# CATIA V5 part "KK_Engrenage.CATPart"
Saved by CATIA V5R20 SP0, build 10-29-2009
Part number: Engrenage
Bounding box of the stored display mesh (mm): x 5 to 10, y 76.002 to 123.998, z -23.997 to 23.997
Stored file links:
  G:\Khaled_CFAO_2011\ST2M\ST2M_GR2\aandujar\Khaled\CAD_thinkMOTION\KK_Engrenage.CATPart
  G:\Khaled_CFAO_2011\ST2M\ST2M_GR2\aandujar\Khaled\CAD_thinkMOTION\KK_Aandujar.CATProduct
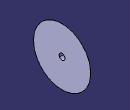
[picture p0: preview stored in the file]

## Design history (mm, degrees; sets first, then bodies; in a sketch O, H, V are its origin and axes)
WSupportSet1: ActiveGrid {3dwsupport RefPoint {point stored without definition}, 3DWOS ({wsupport Support xy-plane, RefPoint {3dwsupport}, GridIn {cartgrid Value 100, Stepbid1 0, Value 100, Stepbid2 0, Direction (1, 0, 0)}, GeometricData ({line type PtDir, Direction (1, 0, 0), Support xy-plane}; {line type PtDir, Direction (0, 1, 0), Support yz-plane})}; {wsupport Support yz-plane, RefPoint {3dwsupport}, GridIn {cartgrid Value 100, Stepbid1 0, Value 100, Stepbid2 0, Direction (0, 1, 0)}, GeometricData ({line type PtDir, Direction (0, 1, 0), Support yz-plane}; {line type PtDir, Direction (0, 0, 1), Support zx-plane})}; {wsupport Support zx-plane, RefPoint {3dwsupport}, GridIn {cartgrid Value 100, Stepbid1 0, Value 100, Stepbid2 0, Direction (0, 0, 1)}, GeometricData ({line type PtDir, Direction (0, 0, 1), Support zx-plane}; {line type PtDir, Direction (1, 0, 0), Support xy-plane})}), GeometricData ({line type PtDir, RefPoint {point stored without definition}, Direction (1, 0, 0), Support xy-plane}; {line type PtDir, RefPoint {point stored without definition}, Direction (0, 1, 0), Support yz-plane}; {line type PtDir, RefPoint {point stored without definition}, Direction (0, 0, 1), Support zx-plane})}
Set1
  Sketch1 on Plane1, origin (0, 0, 0), H (1, 0, 0), V (0, 1, 0)
    point P1 (5, 100)
    line L1 (5, 100) -> (5, 84.6603)
    point P2 (5, 84.6603)
    line L2 (5, 84.6603) -> (10, 76)
    point P3 (10, 76)
    line L3 (10, 76) -> (10, 100)
    line L4 (10, 100) -> (5, 100)
    reference projected point E1 (5, 100) from Point1
    angle L3 L2 = 30
    distance P2 P3 = 10
    distance L4 P3 = 24
    vertical: L1 V
    horizontal: L4 H
    coincidence: P1 E1
Set2
  Plane1 "Plan.Ref4": linked copy from another document
  Point1: linked copy from another document
  Line1 "Axe_pivot_engrenage": linked copy from another document
Body1 (main body)
  Shaft1: profile Sketch1, axis Line1, angle 360
  Sketch2 on face of Shaft1 from Sketch1.L1, origin (5, 100, 0), H (0, 1, 0), V (0, 0, -1)
    point P1 (0, 0)
  Hole1: placed by Sketch2, at (5, 100, 0) direction (1, 0, 0), diameter 5, through (limit type 3)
